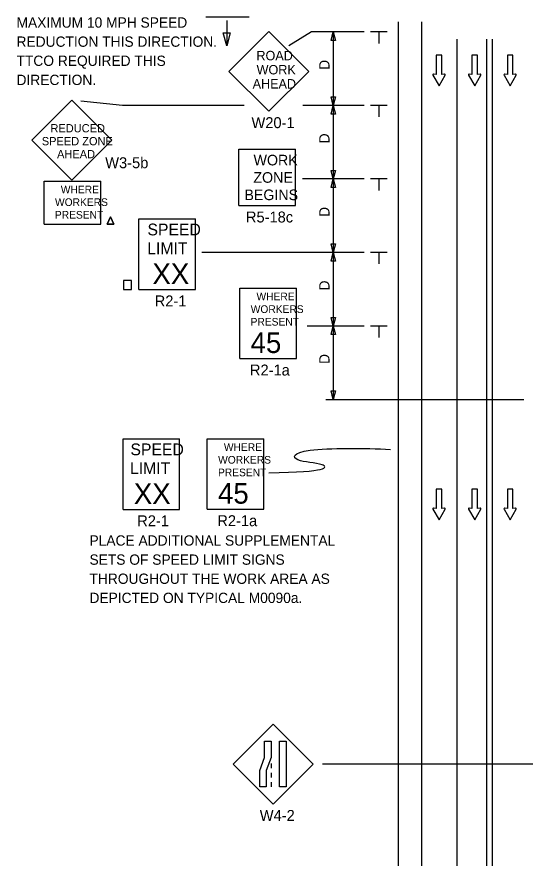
# Model space of a CAD drawing. Extents: x 16727 to 18475, y 5726 to 6927.
# Drawn here: x 16729 to 17074, y 6355 to 6927 of the extents above; entities that cross this region are included whole.
import ezdxf

# ---------------------------------------------------------------- set-up
doc = ezdxf.new("R2010")
doc.units = 0
for name, color, linetype in [('ALI_LEGAL_EX', 7, 'Continuous'), ('MT_SCRATCH_LEVEL_E', 7, 'Continuous'), ('PAVT_EDGE_EX', 7, 'Continuous'), ('TRAFFIC_SIGNS_PR', 7, 'Continuous'), ('TYPICAL_TEXT_DIMEN_PR', 7, 'Continuous')]:
    doc.layers.add(name, color=color, linetype=linetype)

msp = doc.modelspace()

# ---------------------------------------------------------------- linework, layer by layer
at = {"layer": 'ALI_LEGAL_EX'}
for p, q in [((17028.08, 6911.72), (17028.08, 6082.53)), ((17048.08, 6911.72), (17048.08, 6082.53)), ((17052.08, 6911.72), (17052.08, 6082.53))]:
    msp.add_line(p, q, dxfattribs=at)
for points in [[(17028.08, 6911.72), (17028.08, 6886.72)], [(17052.08, 6911.72), (17052.08, 6886.72)], [(17028.08, 6811.72), (17028.08, 6786.72)], [(17052.08, 6811.72), (17052.08, 6786.72)], [(17028.08, 6711.72), (17028.08, 6686.72)], [(17052.08, 6711.72), (17052.08, 6686.72)], [(17028.08, 6611.72), (17028.08, 6586.72)], [(17052.08, 6611.72), (17052.08, 6586.72)], [(17028.08, 6511.72), (17028.08, 6486.72)], [(17052.08, 6511.72), (17052.08, 6486.72)], [(17028.08, 6411.72), (17028.08, 6386.72)], [(17052.08, 6411.72), (17052.08, 6386.72)]]:
    msp.add_lwpolyline(points, dxfattribs=at)
at = {"layer": 'MT_SCRATCH_LEVEL_E'}
for p, q in [((17017.74, 6900.86), (17014, 6900.86)), ((17014, 6900.86), (17014, 6887.6)), ((17017.74, 6900.86), (17014, 6900.86)), ((17014, 6900.86), (17014, 6887.6)), ((17017.74, 6887.6), (17017.74, 6900.86)), ((17017.74, 6887.6), (17017.74, 6900.86)), ((17042, 6900.86), (17038.26, 6900.86)), ((17038.26, 6900.86), (17038.26, 6887.6)), ((17042, 6900.86), (17038.26, 6900.86)), ((17038.26, 6900.86), (17038.26, 6887.6)), ((17042, 6887.6), (17042, 6900.86)), ((17042, 6887.6), (17042, 6900.86)), ((17066.1, 6900.86), (17062.36, 6900.86)), ((17062.36, 6900.86), (17062.36, 6887.6)), ((17066.1, 6900.86), (17062.36, 6900.86)), ((17062.36, 6900.86), (17062.36, 6887.6)), ((17066.1, 6887.6), (17066.1, 6900.86)), ((17066.1, 6887.6), (17066.1, 6900.86)), ((17011.75, 6887.23), (17015.89, 6879.99)), ((17011.75, 6887.23), (17015.89, 6879.99)), ((17014, 6887.6), (17012.23, 6887.91)), ((17014, 6887.6), (17012.23, 6887.91)), ((17015.89, 6879.99), (17020, 6887.23)), ((17015.89, 6879.99), (17020, 6887.23)), ((17019.52, 6887.91), (17017.74, 6887.6)), ((17019.52, 6887.91), (17017.74, 6887.6)), ((17036, 6887.23), (17040.15, 6879.99)), ((17036, 6887.23), (17040.15, 6879.99)), ((17038.26, 6887.6), (17036.48, 6887.91)), ((17038.26, 6887.6), (17036.48, 6887.91)), ((17040.15, 6879.99), (17044.26, 6887.23)), ((17040.15, 6879.99), (17044.26, 6887.23)), ((17043.78, 6887.91), (17042, 6887.6)), ((17043.78, 6887.91), (17042, 6887.6)), ((17060.1, 6887.23), (17064.25, 6879.99)), ((17060.1, 6887.23), (17064.25, 6879.99)), ((17062.36, 6887.6), (17060.58, 6887.91)), ((17062.36, 6887.6), (17060.58, 6887.91)), ((17064.25, 6879.99), (17068.36, 6887.23)), ((17064.25, 6879.99), (17068.36, 6887.23)), ((17067.88, 6887.91), (17066.1, 6887.6)), ((17067.88, 6887.91), (17066.1, 6887.6)), ((17017.74, 6605.79), (17014, 6605.79)), ((17014, 6605.79), (17014, 6592.54)), ((17017.74, 6605.79), (17014, 6605.79)), ((17014, 6605.79), (17014, 6592.54)), ((17017.74, 6592.54), (17017.74, 6605.79)), ((17017.74, 6592.54), (17017.74, 6605.79)), ((17042, 6605.79), (17038.26, 6605.79)), ((17038.26, 6605.79), (17038.26, 6592.54)), ((17042, 6605.79), (17038.26, 6605.79)), ((17038.26, 6605.79), (17038.26, 6592.54)), ((17042, 6592.54), (17042, 6605.79)), ((17042, 6592.54), (17042, 6605.79)), ((17066.1, 6605.79), (17062.36, 6605.79)), ((17062.36, 6605.79), (17062.36, 6592.54)), ((17066.1, 6605.79), (17062.36, 6605.79)), ((17062.36, 6605.79), (17062.36, 6592.54)), ((17066.1, 6592.54), (17066.1, 6605.79)), ((17066.1, 6592.54), (17066.1, 6605.79)), ((17011.75, 6592.17), (17015.89, 6584.93)), ((17011.75, 6592.17), (17015.89, 6584.93)), ((17014, 6592.54), (17012.23, 6592.85)), ((17014, 6592.54), (17012.23, 6592.85)), ((17015.89, 6584.93), (17020, 6592.17)), ((17015.89, 6584.93), (17020, 6592.17)), ((17019.52, 6592.85), (17017.74, 6592.54)), ((17019.52, 6592.85), (17017.74, 6592.54)), ((17036, 6592.17), (17040.15, 6584.93)), ((17036, 6592.17), (17040.15, 6584.93)), ((17038.26, 6592.54), (17036.48, 6592.85)), ((17038.26, 6592.54), (17036.48, 6592.85)), ((17040.15, 6584.93), (17044.26, 6592.17)), ((17040.15, 6584.93), (17044.26, 6592.17)), ((17043.78, 6592.85), (17042, 6592.54)), ((17043.78, 6592.85), (17042, 6592.54)), ((17060.1, 6592.17), (17064.25, 6584.93)), ((17060.1, 6592.17), (17064.25, 6584.93)), ((17062.36, 6592.54), (17060.58, 6592.85)), ((17062.36, 6592.54), (17060.58, 6592.85)), ((17064.25, 6584.93), (17068.36, 6592.17)), ((17064.25, 6584.93), (17068.36, 6592.17)), ((17067.88, 6592.85), (17066.1, 6592.54)), ((17067.88, 6592.85), (17066.1, 6592.54))]:
    msp.add_line(p, q, dxfattribs=at)
for centre, start, end in [((17012.16, 6887.45), 80.0362, 209.7731), ((17012.16, 6887.45), 80.0362, 209.7731), ((17019.6, 6887.45), 330.4248, 99.9638), ((17019.6, 6887.45), 330.4248, 99.9638), ((17036.41, 6887.45), 80.0362, 209.7731), ((17036.41, 6887.45), 80.0362, 209.7731), ((17043.85, 6887.45), 330.4248, 99.9638), ((17043.85, 6887.45), 330.4248, 99.9638), ((17060.51, 6887.45), 80.0362, 209.7731), ((17060.51, 6887.45), 80.0362, 209.7731), ((17067.96, 6887.45), 330.4248, 99.9638), ((17067.96, 6887.45), 330.4248, 99.9638), ((17012.16, 6592.39), 80.0362, 209.7731), ((17012.16, 6592.39), 80.0362, 209.7731), ((17019.6, 6592.39), 330.4248, 99.9638), ((17019.6, 6592.39), 330.4248, 99.9638), ((17036.41, 6592.39), 80.0362, 209.7731), ((17036.41, 6592.39), 80.0362, 209.7731), ((17043.85, 6592.39), 330.4248, 99.9638), ((17043.85, 6592.39), 330.4248, 99.9638), ((17060.51, 6592.39), 80.0362, 209.7731), ((17060.51, 6592.39), 80.0362, 209.7731), ((17067.96, 6592.39), 330.4248, 99.9638), ((17067.96, 6592.39), 330.4248, 99.9638)]:
    msp.add_arc(centre, 0.463, start, end, dxfattribs=at)
at = {"layer": 'PAVT_EDGE_EX'}
for p, q in [((16988.08, 6923.5), (16988.08, 6082.53)), ((17004.08, 6923.5), (17004.08, 6082.53))]:
    msp.add_line(p, q, dxfattribs=at)
at = {"layer": 'TRAFFIC_SIGNS_PR'}
for p, q in [((16900.3, 6916.97), (16873.15, 6889.81)), ((16927.45, 6889.81), (16900.3, 6916.97)), ((16873.15, 6889.81), (16900.3, 6862.66)), ((16900.3, 6862.66), (16927.45, 6889.81)), ((16766.35, 6870.19), (16739.2, 6843.04)), ((16793.51, 6843.04), (16766.35, 6870.19)), ((16739.2, 6843.04), (16766.35, 6815.89)), ((16766.35, 6815.89), (16793.51, 6843.04)), ((16879.88, 6798.5), (16879.88, 6836.9)), ((16879.88, 6836.9), (16918.28, 6836.9)), ((16918.28, 6798.5), (16918.28, 6836.9)), ((16747.6, 6815.19), (16786, 6815.19)), ((16747.6, 6785.88), (16747.6, 6815.19)), ((16786, 6785.88), (16786, 6815.19)), ((16879.88, 6798.5), (16918.28, 6798.5)), ((16747.6, 6785.88), (16786, 6785.88)), ((16812.04, 6789.43), (16850.44, 6789.43)), ((16812.04, 6741.43), (16812.04, 6789.43)), ((16850.44, 6741.43), (16850.44, 6789.43)), ((16812.04, 6741.43), (16850.44, 6741.43)), ((16880.56, 6742.46), (16918.96, 6742.46)), ((16880.56, 6694.46), (16880.56, 6742.46)), ((16918.96, 6694.46), (16918.96, 6742.46)), ((16880.56, 6694.46), (16918.96, 6694.46)), ((16801.22, 6639.93), (16839.62, 6639.93)), ((16801.22, 6591.93), (16801.22, 6639.93)), ((16839.62, 6591.93), (16839.62, 6639.93)), ((16858.41, 6640.01), (16896.81, 6640.01)), ((16858.41, 6592.01), (16858.41, 6640.01)), ((16896.81, 6592.01), (16896.81, 6640.01)), ((16801.22, 6591.93), (16839.62, 6591.93)), ((16858.41, 6592.01), (16896.81, 6592.01)), ((16903.13, 6445.88), (16875.98, 6418.73)), ((16930.28, 6418.73), (16903.13, 6445.88)), ((16901.88, 6419.22), (16901.88, 6416.02)), ((16875.98, 6418.73), (16903.13, 6391.57)), ((16903.13, 6391.57), (16930.28, 6418.73)), ((16901.88, 6412.82), (16901.88, 6409.62)), ((16901.88, 6406.42), (16901.88, 6403.22))]:
    msp.add_line(p, q, dxfattribs=at)
for points in [[(16792.75, 6790.81), (16790.51, 6785.88)], [(16790.51, 6785.88), (16792.75, 6790.81)], [(16794.98, 6785.88), (16792.75, 6790.81)], [(16792.75, 6790.81), (16794.98, 6785.88)], [(16790.51, 6785.88), (16794.98, 6785.88)], [(16794.98, 6785.88), (16790.51, 6785.88)]]:
    msp.add_lwpolyline(points, dxfattribs=at)
for points in [[(16801.43, 6741.43), (16807.02, 6741.43), (16807.02, 6747.6), (16801.43, 6747.6)], [(16901.88, 6434.46), (16901.88, 6423.28), (16898.54, 6414.4), (16898.54, 6403.22), (16894.05, 6403.22), (16894.05, 6414.4), (16897.39, 6423.28), (16897.39, 6434.46)], [(16912.02, 6434.46), (16912.02, 6403.22), (16907.53, 6403.22), (16907.53, 6434.46)]]:
    msp.add_lwpolyline(points, close=True, dxfattribs=at)
at = {"layer": 'TYPICAL_TEXT_DIMEN_PR'}
for p, q in [((16857.5, 6926.9), (16886.94, 6926.9)), ((16871.68, 6924.4), (16871.68, 6907.28)), ((16871.68, 6907.28), (16869.32, 6916.07)), ((16869.32, 6916.07), (16871.68, 6916.07)), ((16871.68, 6916.07), (16874.03, 6916.07)), ((16874.03, 6916.07), (16871.68, 6907.28)), ((16929.27, 6916.65), (16913.92, 6907.23)), ((16965.08, 6916.65), (16929.27, 6916.65)), ((16942.51, 6910.78), (16944.08, 6916.65)), ((16944.08, 6916.65), (16944.08, 6866.65)), ((16944.08, 6916.65), (16945.65, 6910.78)), ((16980.58, 6916.65), (16969.33, 6916.65)), ((16974.95, 6916.65), (16974.95, 6908.86)), ((16944.08, 6910.78), (16942.51, 6910.78)), ((16945.65, 6910.78), (16944.08, 6910.78)), ((16944.08, 6866.65), (16942.51, 6872.51)), ((16942.51, 6872.51), (16944.08, 6872.51)), ((16944.08, 6872.51), (16945.65, 6872.51)), ((16945.65, 6872.51), (16944.08, 6866.65)), ((16800.9, 6866.65), (16772.59, 6869.55)), ((16883.52, 6866.65), (16800.9, 6866.65)), ((16965.08, 6866.65), (16923.32, 6866.65)), ((16942.51, 6860.78), (16944.08, 6866.65)), ((16944.08, 6866.65), (16944.08, 6816.65)), ((16944.08, 6866.65), (16945.65, 6860.78)), ((16980.58, 6866.65), (16969.33, 6866.65)), ((16974.95, 6866.65), (16974.95, 6858.86)), ((16944.08, 6860.78), (16942.51, 6860.78)), ((16945.65, 6860.78), (16944.08, 6860.78)), ((16944.08, 6816.65), (16942.51, 6822.51)), ((16942.51, 6822.51), (16944.08, 6822.51)), ((16944.08, 6822.51), (16945.65, 6822.51)), ((16945.65, 6822.51), (16944.08, 6816.65)), ((16965.08, 6816.65), (16923.13, 6816.65)), ((16942.51, 6810.78), (16944.08, 6816.65)), ((16944.08, 6816.65), (16944.08, 6766.65)), ((16944.08, 6816.65), (16945.65, 6810.78)), ((16980.58, 6816.65), (16969.33, 6816.65)), ((16974.95, 6816.65), (16974.95, 6808.86)), ((16944.08, 6810.78), (16942.51, 6810.78)), ((16945.65, 6810.78), (16944.08, 6810.78)), ((16944.08, 6766.65), (16942.51, 6772.51)), ((16942.51, 6772.51), (16944.08, 6772.51)), ((16944.08, 6772.51), (16945.65, 6772.51)), ((16945.65, 6772.51), (16944.08, 6766.65)), ((16965.08, 6766.65), (16854.83, 6766.65)), ((16942.51, 6760.78), (16944.08, 6766.65)), ((16944.08, 6766.65), (16944.08, 6716.65)), ((16944.08, 6766.65), (16945.65, 6760.78)), ((16980.58, 6766.65), (16969.33, 6766.65)), ((16974.95, 6766.65), (16974.95, 6758.86)), ((16944.08, 6760.78), (16942.51, 6760.78)), ((16945.65, 6760.78), (16944.08, 6760.78)), ((16944.08, 6716.65), (16942.51, 6722.51)), ((16942.51, 6722.51), (16944.08, 6722.51)), ((16944.08, 6722.51), (16945.65, 6722.51)), ((16945.65, 6722.51), (16944.08, 6716.65)), ((16965.08, 6716.65), (16926.2, 6716.65)), ((16942.51, 6710.78), (16944.08, 6716.65)), ((16944.08, 6716.65), (16944.08, 6666.65)), ((16944.08, 6716.65), (16945.65, 6710.78)), ((16980.58, 6716.65), (16969.33, 6716.65)), ((16974.95, 6716.65), (16974.95, 6708.86)), ((16944.08, 6710.78), (16942.51, 6710.78)), ((16945.65, 6710.78), (16944.08, 6710.78)), ((16944.08, 6666.65), (16942.51, 6672.51)), ((16942.51, 6672.51), (16944.08, 6672.51)), ((16944.08, 6672.51), (16945.65, 6672.51)), ((16945.65, 6672.51), (16944.08, 6666.65)), ((16939.08, 6666.65), (17073.46, 6666.65)), ((16936.74, 6419.03), (17084.27, 6419.03))]:
    msp.add_line(p, q, dxfattribs=at)
msp.add_open_spline([(16900.17, 6616.82), (16941.13, 6617.47), (16940.2, 6623.91), (16916.01, 6623.91), (16916.01, 6633.81), (16965.65, 6633.81), (16982.82, 6632.76)], degree=3, dxfattribs=at)

# ---------------------------------------------------------------- texts
at = {"layer": 'TRAFFIC_SIGNS_PR'}
for s, height, p in [('ROAD', 6.4, (16891.84, 6897.35)), ('WORK', 6.4, (16891.95, 6887.75)), ('AHEAD', 6.4, (16889.26, 6878.15)), ('REDUCED', 5.6, (16751.88, 6848.35)), ('W20-1', 7.44, (16888.47, 6851.22)), ('SPEED ZONE', 5.6, (16746, 6839.55)), ('AHEAD', 5.6, (16756.37, 6830.75)), ('W3-5b', 7.44, (16789.09, 6823.96)), ('WORK', 7.217, (16889.88, 6825.87)), ('ZONE', 7.217, (16889.76, 6814.06)), ('WHERE', 5.2, (16758.91, 6806.88)), ('BEGINS', 7.217, (16883.69, 6802.25)), ('WORKERS', 5.2, (16754.98, 6798.28)), ('PRESENT', 5.2, (16754.91, 6789.68)), ('R5-18c', 7.44, (16884.69, 6787.06)), ('SPEED', 8, (16817.81, 6778.3)), ('LIMIT', 8, (16817.64, 6765.5)), ('XX', 14.031, (16821.15, 6745.19)), ('WHERE', 5.2, (16891.87, 6734.15)), ('R2-1', 7.44, (16822.72, 6729.99)), ('WORKERS', 5.2, (16887.95, 6725.55)), ('PRESENT', 5.2, (16887.88, 6716.95)), ('45', 14.031, (16887.87, 6698.32)), ('R2-1a', 7.44, (16887.42, 6683.02)), ('SPEED', 8, (16806.25, 6628.79)), ('WHERE', 5.2, (16869.72, 6631.7)), ('WORKERS', 5.2, (16865.8, 6623.1)), ('LIMIT', 8, (16805.92, 6615.99)), ('PRESENT', 5.2, (16865.73, 6614.5)), ('XX', 14.031, (16808.53, 6595.68)), ('45', 14.031, (16865.72, 6595.87)), ('R2-1', 7.44, (16810.83, 6580.49)), ('R2-1a', 7.44, (16865.27, 6580.57)), ('PLACE ADDITIONAL SUPPLEMENTAL', 7, (16778.41, 6567.32)), ('SETS OF SPEED LIMIT SIGNS', 7, (16778.41, 6554.32)), ('THROUGHOUT THE WORK AREA AS', 7, (16778.41, 6541.32)), ('DEPICTED ON TYPICAL M0090a.', 7, (16778.41, 6528.32)), ('W4-2', 7.44, (16894.09, 6380.13))]:
    msp.add_text(s, height=height, dxfattribs=at).set_placement(p)
at = {"layer": 'TYPICAL_TEXT_DIMEN_PR'}
for s, p in [('MAXIMUM 10 MPH SPEED', (16728.83, 6919.53)), ('REDUCTION THIS DIRECTION.', (16728.83, 6906.53)), ('TTCO REQUIRED THIS', (16728.83, 6893.53)), ('DIRECTION.', (16728.83, 6880.53))]:
    msp.add_text(s, height=7, dxfattribs=at).set_placement(p)
for p in [(16941.52, 6890.86), (16941.52, 6840.86), (16941.52, 6790.86), (16941.52, 6740.86), (16941.52, 6690.86)]:
    msp.add_text('D', height=7, rotation=90, dxfattribs=at).set_placement(p)

doc.saveas('drawing.dxf')
